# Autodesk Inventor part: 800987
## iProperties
Created: 2007-10
Part Number: 800987
Document SubType Name: Modeling
Designer: TH
Density: 7.85 g/cm^3
Mass: 11.8933 g
Surface Area: 10.7394 cm^2
Volume: 1.51507 cm^3
Material: Steel
Description: CONNECTOR PIN
Component Category: Fasteners
Author: TH
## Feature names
1. Revolution1
2. Extrusion1
3. Extrusion2
4. Fillet1
5. Fillet2
6. Fillet3
